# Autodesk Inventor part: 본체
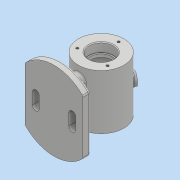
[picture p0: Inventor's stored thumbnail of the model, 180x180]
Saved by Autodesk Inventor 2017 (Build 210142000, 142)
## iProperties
Part Number: 본체
Material: 일반
Document SubType Name: Modeling
Designer: 601-07
Density: 1 g/cm^3
Appearance: 기본값
Mass: 183.424 g
Surface Area: 489.75 cm^2
Volume: 183.424 cm^3
Author: 601-07
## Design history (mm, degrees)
sketch "스케치1"
  geometry: C1 r 30 at (0, 0); 1 further point
  constraints: 1 centre point, 1 coincident
  dimensions: "d0" = 60 diameter of C1
extrude "돌출1" new body sketch "스케치1" stored distance "d1" = 72; taper "d2" = 0 deg
node "작업 평면1"
sketch "스케치2"
  geometry: L1 (38, 35.496)-(-38, 35.496); L2 (-38, 35.496)-(-38, -35.496); L3 (-38, -35.496)-(38, -35.496); L4 (38, -35.496)-(38, 35.496); A1 r 52 centre (0, 0) between (38, 35.496) and (-38, 35.496); A2 r 52 centre (0, 0) between (-38, -35.496) and (38, -35.496); 1 further point
  constraints: 8 end point, 4 point on circle, 2 centre point, 2 parallel, 1 coincident, 1 horizontal, 1 perpendicular
  dimensions: "d5" = 76 distance of L1.start L1.end; "d6" = 52 radius of A2; "d7" = 52 radius of A1
extrude "돌출2" join sketch "스케치2" distance "d8" = 10; taper "d9" = 0 deg
sketch "스케치3"
  geometry: L1 (0, -19)-(0, 19); L2 (7, -19)-(7, 19); L3 (-7, 19)-(-7, -19); A1 r 7 centre (0, -19) between (-7, -19) and (7, -19); A2 r 7 centre (0, 19) between (7, 19) and (-7, 19); 2 further points
  constraints: 8 end point, 4 point on circle, 4 tangent, 2 centre point, 1 coincident, 1 midpoint, 1 parallel, 1 vertical
  dimensions: "d10" = 38 distance of L1.start L1.end; "d11" = 14 distance between parallel lines of L2 L3
extrude "돌출3" join sketch "스케치3" stored distance "d12" = 10; taper "d13" = 0 deg
sketch "스케치4"
  geometry: C1 r 16 at (0, 0); 1 further point
  constraints: 1 centre point, 1 coincident
  dimensions: "d14" = 32 diameter of C1
extrude "돌출4" cut sketch "스케치4" distance "d15" = 12; taper "d16" = 0 deg
sketch "스케치5"
  geometry: C1 r 14 at (0, 0); 1 further point
  constraints: 1 centre point, 1 coincident
  dimensions: "d17" = 28 diameter of C1
extrude "돌출5" cut sketch "스케치5" distance "d18" = 4; taper "d19" = 0 deg
sketch "스케치6"
  geometry: C1 r 25 at (0, 0); 1 further point
  constraints: 1 centre point, 1 coincident
  dimensions: "d20" = 50 diameter of C1
extrude "돌출6" cut sketch "스케치6" distance "d21" = 40; taper "d22" = 0 deg
sketch "스케치7"
  geometry: C1 r 14 at (0, 0); 1 further point
  constraints: 1 centre point, 1 coincident
  dimensions: "d23" = 28 diameter of C1
extrude "돌출7" cut sketch "스케치7" distance "d24" = 4; taper "d25" = 0 deg
sketch "스케치8"
  geometry: C1 r 16 at (0, 0); 1 further point
  constraints: 1 centre point, 1 coincident
  dimensions: "d26" = 32 diameter of C1
extrude "돌출8" cut sketch "스케치8" distance "d27" = 12; taper "d28" = 0 deg
sketch "스케치9"
  geometry: 2 further points
  constraints: 1 vertical alignment
  dimensions: "d29" = 23 distance of point (0, 0) point (0, 23)
hole "구멍1" sketch "스케치9" at (0, 23) diameter "d30" = 3.242; stored, may be unused: countersink angle "d34" = 90 deg, drill point angle "d36" = 118 deg; dims "d31" = 8, "d32" = 4, "d33" = 2, "d35" = 10
chamfer "모따기1" distance "d40" = 1; stored, may be unused: second distance "d41" = 2, angle "d42" = 45 deg
fillet "모깎기1" dims "d43" = 0.3
fillet "모깎기2" dims "d44" = 3
sketch "스케치11"
  geometry: L1 (0, 0)-(0, 37.076); L2 (0, 0)-(16.5, 28.579)
  constraints: 4 end point, 1 vertical
  dimensions: "d45" = 33 distance of L1.start L2.end; "d46" = 30 deg angle of L1 L2
node "작업 평면2"
sketch "스케치12"
  geometry: C1 r 8 at (0, 0); 1 further point
  constraints: 1 centre point, 1 coincident
  dimensions: "d47" = 16 diameter of C1
extrude "돌출9" join sketch "스케치12" stored distance "d48" = 6.25; taper "d49" = 0 deg
sketch "스케치13"
  geometry: C1 r 4 at (0, 0); 1 further point
  constraints: 1 centre point, 1 coincident
  dimensions: "d50" = 8 diameter of C1
extrude "돌출10" cut sketch "스케치13" distance "d51" = 16.5; taper "d52" = 0 deg
fillet "모깎기3" dims "d53" = 1
sketch "스케치14"
  geometry: L1 (-24, -7.5)-(-24, 7.5); L2 (-19.5, -7.5)-(-19.5, 7.5); L3 (-28.5, 7.5)-(-28.5, -7.5); A1 r 4.5 centre (-24, -7.5) between (-28.5, -7.5) and (-19.5, -7.5); A2 r 4.5 centre (-24, 7.5) between (-19.5, 7.5) and (-28.5, 7.5); 2 further points
  constraints: 8 end point, 4 point on circle, 4 tangent, 2 centre point, 1 horizontal alignment, 1 midpoint, 1 parallel, 1 vertical
  dimensions: "d57" = 9 distance between parallel lines of L2 L3; "d58" = 15 distance of L1.start L1.end; "d59" = 24 distance from line of point (0, 0) L1
extrude "돌출11" cut sketch "스케치14" distance "d60" = 16.5; taper "d61" = 0 deg
fillet "모깎기4" dims "d62" = 3
fillet "모깎기5" dims "d63" = 3
sketch "스케치15"
  geometry: C1 r 42.5 at (0, 0); 1 further point
  constraints: 1 centre point, 1 coincident, 1 other
  dimensions: "d64" = 85 diameter of C1
feature "엠보싱1" sketch "스케치15" dims "d65" = 0.5, "d66" = 0
fillet "모깎기6" dims "d67" = 3
fillet "모깎기7" dims "d68" = 1
node "솔리드1"
pattern_circular "원형 패턴1" dims angle "d38" = 360 deg
mirror "미러1"
mirror "미러2"
other parameters: "d3" = -62, "d4" = 104
